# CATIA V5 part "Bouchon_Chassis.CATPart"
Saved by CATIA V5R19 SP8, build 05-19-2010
Part number: Bouchon_Chassis
Nomenclature: 43
Material "Plastique": density 1200 kg/m3, Young's modulus 2.2e+09 Pa, Poisson ratio 0.38, thermal expansion 6.84e-05 1/K
Bounding box of the stored display mesh (mm): x -20 to 20, y -2 to 25, z -20 to 20
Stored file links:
  C:\Users\rphgr\Desktop\0_Tapis_TC520B_vitesse\Bouchon_Chassis.CATPart
  D:\Documents\1_Travail\1 - ac-limoges.fr\ac-limoges.fr\Emmanuel Maynard - STI2D_Turgot\3 - Supports\Tapis de course TC520B\Tapis_TC520B.CATProduct
  D:\Documents\1_Travail\1 - ac-limoges.fr\ac-limoges.fr\Emmanuel Maynard - STI2D_Turgot\3 - Supports\Tapis de course TC520B\Tapis de course TC520B_Ca\Cadre Chasis (1).CATPart
  D:\Programmes\DassaultSysteme\win_b64\startup\materials\French\Catalog.CATMaterial
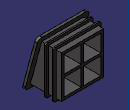
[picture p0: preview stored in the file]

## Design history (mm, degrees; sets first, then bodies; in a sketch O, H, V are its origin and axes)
AxisSystem1: origin (0, 0, 0), X (1, 0, 0), Y (0, 1, 0), Z (0, 0, 1)
Set1
  DatumSurface1
  DatumCurve1 to DatumCurve9
Body1 (main body), material "Plastique"
  Sketch1 on ZX plane of AxisSystem1, origin (0, 0, 0), H (0, 0, 1), V (1, 0, 0)
    line L1 (16.3, 16.3) -> (16.3, -16.3)
    line L2 (16.3, -16.3) -> (-16.3, -16.3)
    line L3 (-16.3, -16.3) -> (-16.3, 16.3)
    line L4 (-16.3, 16.3) -> (16.3, 16.3)
    distance L4 L2 = 32.6
    distance L3 L1 = 32.6
    vertical: L1 V, L3 V
    horizontal: L2 H, L4 H
    equidistance: L1 L3 O, L2 L4 O
  Pad1: profile Sketch1, direction (0, 1, 0), length 25, thin wall 2
  Sketch2 on face of Pad1, origin (-16.3, 0, 0), H (0, -1, 0), V (0, 0, 1)
    line L1 (-10.2443, 18.2322) -> (-0.2552, -19.0474)
    reference intersected line E1 (0, -20) -> (-0.4555, -18.3) from face of DatumSurface1
    coincidence: L1 E1
  Pocket1: profile Sketch2, direction (1, 0, 0), through (limit type 3)
  Sketch3 on face of Pocket1 from Sketch2.L1, origin (0, 5, -1.3397), H (1, 0, 0), V (0, 0.2588, 0.9659)
    projected line E1 (20, 18.9867) -> (20, -16.2127) from edge of DatumCurve1
    projected curve E2 from edge of DatumCurve2
    projected line E3 (17, 22.0925) -> (-17, 22.0925) from edge of DatumCurve3
    projected curve E4 from edge of DatumCurve4
    projected line E5 (-20, 18.9867) -> (-20, -16.2127) from edge of DatumCurve5
    projected curve E6 from edge of DatumCurve6
    projected line E7 (17, -19.3185) -> (-17, -19.3185) from edge of DatumCurve7
    projected curve E8 from edge of DatumCurve8
  Pad2: profile Sketch3, direction along edge of DatumCurve9 reversed, length 2
  Sketch4 on end face of Pad1, origin (0, 25, 0), H (-1, 0, 0), V (0, 0, 1)
    line L1 (1, 14.3) -> (1, 1)
    line L2 (1, -14.3) -> (-1, -14.3)
    line L3 (-1, -14.3) -> (-1, -1)
    line L4 (-1, 14.3) -> (1, 14.3)
    reference intersected line E1 (14.3, 14.3) -> (-14.3, 14.3) from face of Pad1
    line L5 (14.3, 1) -> (14.3, -1)
    line L6 (14.3, -1) -> (1, -1)
    line L7 (-14.3, -1) -> (-14.3, 1)
    line L8 (-14.3, 1) -> (-1, 1)
    reference intersected line E2 (14.3, -14.3) -> (14.3, 14.3) from face of Pad1
    point P9 (-1, 1)
    line L9 (1, 1) -> (14.3, 1)
    point P11 (-1, -1)
    line L10 (-1, 1) -> (-1, 14.3)
    line L11 (1, -1) -> (1, -14.3)
    line L12 (-1, -1) -> (-14.3, -1)
    distance L3 L1 = 2
    distance L6 L8 = 2
    vertical: L1 V, L3 V, L5 V, L7 V, L10 V, L11 V
    horizontal: L2 H, L4 H, L6 H, L8 H, L9 H, L12 H
    equidistance: L1 L3 O, L2 L4 O, L5 L7 O, L6 L8 O
    coincidence: L4 E1, L5 E2, L3 P9, L8 L9, L6 P11, L3 L10, L1 L11, L6 L12
  Pad3: profile Sketch4, direction (0, 1, 0), up to start face of Pad2
  Plane1: type Offset, RefPlane face of Pad3, Offset 5
  Sketch5 on YZ plane of AxisSystem1, origin (0, 0, 0), H (0, 1, 0), V (0, 0, 1)
    line L1 (20, 16.3) -> (21, 16.3)
    line L2 (21, 16.3) -> (21, 18.3)
    line L3 (21, 18.3) -> (20, 18.3)
    line L4 (20, 18.3) -> (20, 16.3)
    point P5 (14, 16.3)
    line L5 (14, 16.3) -> (15, 16.3)
    line L6 (15, 16.3) -> (15, 18.3)
    line L7 (15, 18.3) -> (14, 18.3)
    line L8 (14, 18.3) -> (14, 16.3)
    point P7 (15, 18.3)
    reference intersected line E1 (0, 16.3) -> (25, 16.3) from face of Pad1
    reference intersected line E2 through (20, 0) direction (0, -1) from Plane1
    distance L3 L1 = 2
    distance L4 L2 = 1
    distance L8 L6 = 1
    distance L6 L4 = 5
    horizontal: L1 H, L3 H, L5 H, L7 H
    vertical: L2 V, L4 V, L6 V, L8 V
    coincidence: P5 L1, P7 L3, L1 E1, L3 L7, L4 E2
  Sketch6 on Plane1, origin (0, 20, 0), H (1, 0, 0), V (0, 0, 1)
    projected line E1 (-16.3, 16.3) -> (-16.3, -16.3) from face of Pad1
    projected line E2 (16.3, 16.3) -> (-16.3, 16.3) from face of Pad1
    projected line E3 (16.3, -16.3) -> (16.3, 16.3) from face of Pad1
    projected line E4 (-16.3, -16.3) -> (16.3, -16.3) from face of Pad1
  Rib1: profile Sketch5, centre curve Sketch6
  Fillet1: radius 1.25, on edge [face of Rib1 | face of Rib1] (x8)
